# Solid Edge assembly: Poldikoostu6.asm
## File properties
Author: Türk
Template: Iso Assembly.asm
Last saved by: Türk
Revision: 2
Application: Solid Edge
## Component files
Polt110x20.par
Mutter.par
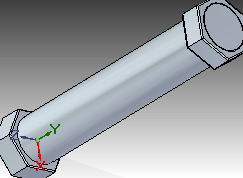
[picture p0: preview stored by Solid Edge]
